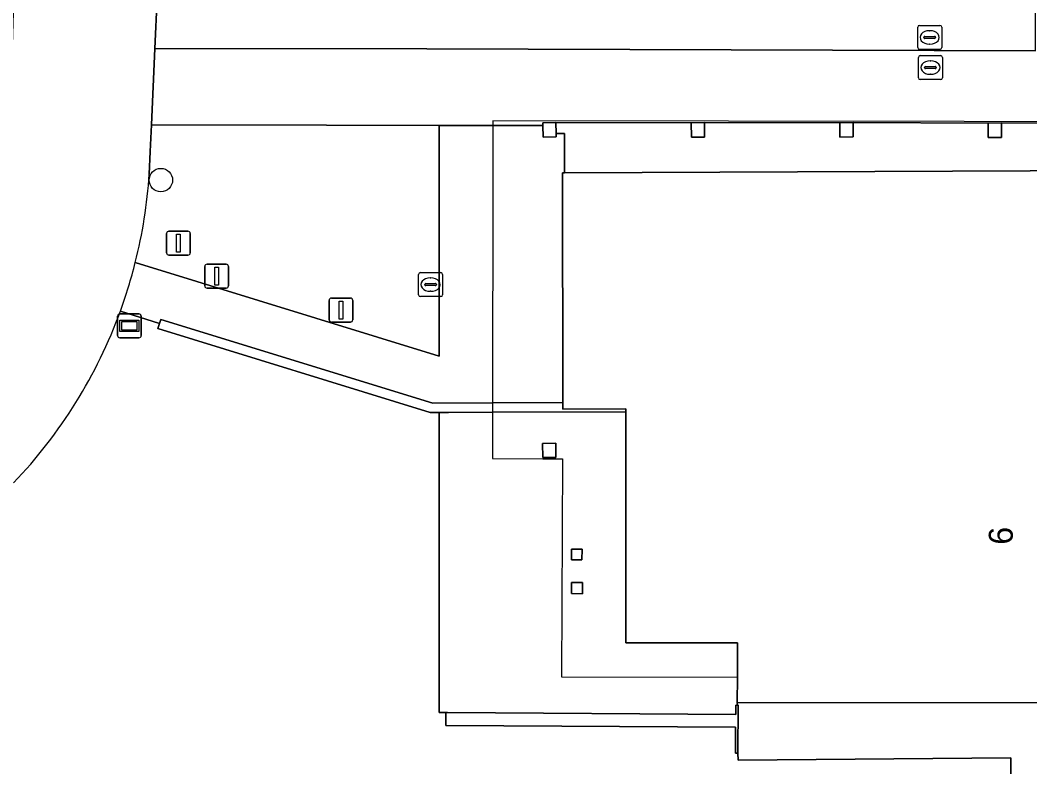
# Model space of a CAD drawing. Extents: x 161477 to 163040, y 383680 to 384871.
# Drawn here: x 161717.63 to 161759.79, y 384128.63 to 384159.8 of the extents above; entities that cross this region are included whole.
import ezdxf

# ---------------------------------------------------------------- set-up
doc = ezdxf.new("R2010")
doc.units = 0
for name, color, linetype in [('IMGEO_Boom', 7, 'Continuous'), ('IMGEO_Groenvoorziening', 7, 'Continuous'), ('IMGEO_Informatiebord', 7, 'Continuous'), ('IMGEO_Lichtmast', 7, 'Continuous'), ('IMGEO_Muur', 7, 'Continuous'), ('IMGEO_Pand', 7, 'Continuous'), ('IMGEO_Pand_nummerreeks', 7, 'Continuous'), ('IMGEO_Pand_overbouw', 7, 'Continuous'), ('IMGEO_Rioolput', 7, 'Continuous'), ('IMGEO_Vlaggenmast', 7, 'Continuous'), ('IMGEO_Voetpad_gesloten', 7, 'Continuous'), ('IMGEO_Voetpad_open', 7, 'Continuous')]:
    doc.layers.add(name, color=color, linetype=linetype)

msp = doc.modelspace()

# ---------------------------------------------------------------- linework, layer by layer
at = {"layer": 'IMGEO_Boom'}
msp.add_circle((161723.508, 384153.124), 0.489, dxfattribs=at)
at = {"layer": 'IMGEO_Groenvoorziening'}
for points in [[(161759.977, 384188.732), (161759.976, 384189.513), (161744.828, 384189.533), (161743.11, 384189.23), (161740.985, 384188.366), (161732.479, 384184.27), (161729.725, 384182.49), (161727.866, 384180.984), (161726.316, 384179.346), (161725.221, 384177.344), (161724.224, 384175.071), (161723.737, 384172.104), (161723.605, 384166.648), (161723.598, 384166.489), (161723.448, 384163.067), (161723.347, 384160.739), (161723.254, 384158.616), (161734.619, 384158.605), (161760.033, 384158.521), (161760.032, 384158.93)], [(161765.899, 384126.429), (161761.389, 384126.458), (161761.398, 384131.31), (161747.578, 384131.312), (161747.589, 384131.203), (161747.612, 384131.203), (161747.599, 384129.203), (161747.606, 384128.913), (161758.995, 384129.011), (161759.044, 384124.455), (161763.654, 384124.37), (161763.216, 384099.214), (161762.895, 384081.151), (161762.894, 384080.681), (161765.84, 384080.732)]]:
    msp.add_lwpolyline(points, close=True, dxfattribs=at)
for points in [[(161722.441, 384149.683), (161735.127, 384145.767), (161735.126, 384152.183), (161735.126, 384155.407)], [(161735.126, 384155.407), (161730.422, 384155.415), (161723.115, 384155.427), (161723.066, 384154.311), (161723.025, 384153.368)], [(161765.94, 384080.732), (161765.84, 384080.732), (161762.894, 384080.681), (161762.895, 384081.151), (161763.216, 384099.214), (161763.654, 384124.37), (161759.044, 384124.455), (161758.995, 384129.011), (161747.606, 384128.913), (161747.599, 384129.203), (161747.499, 384129.203), (161747.506, 384130.293), (161735.408, 384130.355), (161735.401, 384130.9), (161735.134, 384130.899), (161735.134, 384143.421), (161734.757, 384143.42), (161723.376, 384146.927), (161723.45, 384147.142), (161721.817, 384147.658)]]:
    msp.add_lwpolyline(points, dxfattribs=at)
for centre, radius, start, end in [((161702.337, 384154.758), 20.735, 345.8327, 356.1565), ((161702.413, 384154.74), 20.656, 316.3499, 339.9499)]:
    msp.add_arc(centre, radius, start, end, dxfattribs=at)
at = {"layer": 'IMGEO_Informatiebord'}
for p, q in [((161721.697, 384146.638), (161721.697, 384147.438)), ((161721.697, 384147.438), (161721.697, 384146.638)), ((161721.797, 384147.538), (161722.587, 384147.538)), ((161722.587, 384147.538), (161721.797, 384147.538)), ((161722.687, 384147.438), (161722.687, 384146.638)), ((161722.687, 384146.638), (161722.687, 384147.438)), ((161722.587, 384146.538), (161721.797, 384146.538)), ((161721.797, 384146.538), (161722.587, 384146.538))]:
    msp.add_line(p, q, dxfattribs=at)
for points in [[(161721.798, 384147.27), (161722.586, 384147.27), (161722.586, 384146.806), (161721.798, 384146.806), (161721.798, 384147.27)], [(161721.863, 384147.205), (161721.863, 384146.871), (161722.521, 384146.871), (161722.521, 384147.205), (161721.863, 384147.205)]]:
    msp.add_lwpolyline(points, dxfattribs=at)
for centre, start, end in [((161721.797, 384147.438), 90, 180), ((161721.797, 384147.438), 90, 180), ((161722.587, 384147.438), 0, 90), ((161722.587, 384147.438), 360, 90), ((161721.797, 384146.638), 180, 270), ((161721.797, 384146.638), 180, 270), ((161722.587, 384146.638), 270, 0), ((161722.587, 384146.638), 270, 0)]:
    msp.add_arc(centre, 0.1, start, end, dxfattribs=at)
at = {"layer": 'IMGEO_Lichtmast'}
for p, q in [((161723.745, 384150.09), (161723.745, 384150.89)), ((161723.745, 384150.89), (161723.745, 384150.09)), ((161723.845, 384150.99), (161724.635, 384150.99)), ((161724.635, 384150.99), (161723.845, 384150.99)), ((161724.735, 384150.89), (161724.735, 384150.09)), ((161724.735, 384150.09), (161724.735, 384150.89)), ((161724.635, 384149.99), (161723.845, 384149.99)), ((161723.845, 384149.99), (161724.635, 384149.99))]:
    msp.add_line(p, q, dxfattribs=at)
msp.add_lwpolyline([(161724.165, 384150.865), (161724.315, 384150.865), (161724.315, 384150.115), (161724.165, 384150.115), (161724.165, 384150.865)], dxfattribs=at)
for centre, start, end in [((161723.845, 384150.89), 90, 180), ((161723.845, 384150.89), 90, 180), ((161724.635, 384150.89), 0, 90), ((161724.635, 384150.89), 360, 90), ((161723.845, 384150.09), 180, 270), ((161723.845, 384150.09), 180, 270), ((161724.635, 384150.09), 270, 0), ((161724.635, 384150.09), 270, 0)]:
    msp.add_arc(centre, 0.1, start, end, dxfattribs=at)
at = {"layer": 'IMGEO_Muur'}
for points in [[(161723.506, 384147.305), (161723.45, 384147.142), (161723.376, 384146.927), (161734.757, 384143.42), (161735.134, 384143.421), (161735.512, 384143.423), (161737.356, 384143.43), (161742.917, 384143.452), (161742.917, 384143.573), (161740.291, 384143.568), (161740.291, 384143.838), (161737.357, 384143.825), (161734.857, 384143.814)], [(161747.612, 384131.203), (161747.589, 384131.203), (161747.512, 384131.203), (161747.51, 384130.823), (161735.483, 384130.899), (161735.401, 384130.9), (161735.408, 384130.355), (161747.506, 384130.293), (161747.499, 384129.203), (161747.599, 384129.203)]]:
    msp.add_lwpolyline(points, close=True, dxfattribs=at)
at = {"layer": 'IMGEO_Pand'}
for points in [[(161740.002, 384155.523), (161739.452, 384155.511), (161739.455, 384155.4), (161739.466, 384154.911), (161740.016, 384154.923), (161740.013, 384155.064)], [(161746.206, 384155.521), (161745.653, 384155.516), (161745.658, 384154.916), (161746.211, 384154.921)], [(161752.409, 384155.523), (161751.854, 384155.519), (161751.858, 384154.919), (161752.413, 384154.923)], [(161758.603, 384155.507), (161758.052, 384155.506), (161758.053, 384154.906), (161758.604, 384154.907)], [(161739.996, 384142.137), (161739.446, 384142.131), (161739.453, 384141.541), (161740.003, 384141.547)], [(161741.094, 384137.717), (161740.654, 384137.719), (161740.652, 384137.279), (161741.092, 384137.277)], [(161741.116, 384136.327), (161740.649, 384136.329), (161740.647, 384135.862), (161741.114, 384135.86)]]:
    msp.add_lwpolyline(points, close=True, dxfattribs=at)
msp.add_lwpolyline([(161763.052, 384153.523), (161740.363, 384153.423), (161740.284, 384153.423), (161740.291, 384143.838), (161740.291, 384143.568), (161742.917, 384143.573), (161742.917, 384143.452), (161742.924, 384133.809), (161747.583, 384133.803), (161747.58, 384132.381), (161747.578, 384131.312), (161761.398, 384131.31)], dxfattribs=at)
at = {"layer": 'IMGEO_Pand_overbouw'}
msp.add_lwpolyline([(161766.891, 384155.558), (161737.37, 384155.593), (161737.37, 384155.486), (161737.354, 384141.498), (161739.454, 384141.495), (161740.281, 384141.494), (161740.235, 384132.393), (161747.58, 384132.381), (161747.583, 384133.803), (161742.924, 384133.809), (161742.917, 384143.452), (161742.917, 384143.573), (161740.291, 384143.568), (161740.291, 384143.838), (161740.284, 384153.423), (161763.052, 384153.523)], dxfattribs=at)
at = {"layer": 'IMGEO_Rioolput'}
for p, q in [((161755.109, 384158.654), (161755.109, 384159.506)), ((161755.184, 384159.58), (161756.036, 384159.58)), ((161755.597, 384159.36), (161755.622, 384159.36)), ((161756.11, 384159.506), (161756.11, 384158.654)), ((161755.368, 384159.074), (161755.368, 384159.086)), ((161755.806, 384159.037), (161755.408, 384159.037)), ((161755.411, 384159.123), (161755.809, 384159.123)), ((161755.852, 384159.086), (161755.852, 384159.074)), ((161756.036, 384158.58), (161755.184, 384158.58)), ((161755.62, 384158.8), (161755.595, 384158.8)), ((161755.139, 384157.394), (161755.139, 384158.246)), ((161755.214, 384158.32), (161756.066, 384158.32)), ((161755.627, 384158.1), (161755.652, 384158.1)), ((161756.14, 384158.246), (161756.14, 384157.394)), ((161755.398, 384157.814), (161755.398, 384157.826)), ((161755.836, 384157.777), (161755.438, 384157.777)), ((161755.441, 384157.863), (161755.839, 384157.863)), ((161755.882, 384157.826), (161755.882, 384157.814)), ((161756.066, 384157.32), (161755.214, 384157.32)), ((161755.65, 384157.54), (161755.625, 384157.54)), ((161734.269, 384148.334), (161734.269, 384149.186)), ((161734.344, 384149.26), (161735.196, 384149.26)), ((161735.27, 384149.186), (161735.27, 384148.334)), ((161734.528, 384148.754), (161734.528, 384148.766)), ((161734.966, 384148.717), (161734.568, 384148.717)), ((161734.571, 384148.803), (161734.969, 384148.803)), ((161734.757, 384149.04), (161734.782, 384149.04)), ((161735.012, 384148.766), (161735.012, 384148.754)), ((161734.78, 384148.48), (161734.755, 384148.48)), ((161735.196, 384148.26), (161734.344, 384148.26))]:
    msp.add_line(p, q, dxfattribs=at)
for points in [[(161755.109, 384158.654), (161755.109, 384159.506)], [(161755.184, 384159.58), (161756.036, 384159.58)], [(161756.11, 384159.506), (161756.11, 384158.654)], [(161756.036, 384158.58), (161755.184, 384158.58)], [(161755.139, 384157.394), (161755.139, 384158.246)], [(161755.214, 384158.32), (161756.066, 384158.32)], [(161756.14, 384158.246), (161756.14, 384157.394)], [(161756.066, 384157.32), (161755.214, 384157.32)], [(161734.269, 384148.334), (161734.269, 384149.186)], [(161734.344, 384149.26), (161735.196, 384149.26)], [(161735.27, 384149.186), (161735.27, 384148.334)], [(161735.196, 384148.26), (161734.344, 384148.26)]]:
    msp.add_lwpolyline(points, dxfattribs=at)
for centre, radius, start, end in [((161755.186, 384159.504), 0.0765, 91.552, 178.448), ((161755.186, 384159.504), 0.0765, 91.552, 178.448), ((161756.034, 384159.504), 0.0765, 1.552, 88.448), ((161756.034, 384159.504), 0.0765, 1.552, 88.448), ((161755.408, 384159.083), 0.0403, 85.8775, 175.7526), ((161755.405, 384159.073), 0.0366, 178.938, 274.7102), ((161755.809, 384159.08), 0.043, 264.8664, 352.4533), ((161755.813, 384159.085), 0.0386, 1.7309, 96.639), ((161755.186, 384158.656), 0.0765, 181.552, 268.448), ((161755.186, 384158.656), 0.0765, 181.552, 268.448), ((161756.034, 384158.656), 0.0765, 271.552, 358.448), ((161756.034, 384158.656), 0.0765, 271.552, 358.448), ((161755.216, 384158.244), 0.0765, 91.552, 178.448), ((161755.216, 384158.244), 0.0765, 91.552, 178.448), ((161756.064, 384158.244), 0.0765, 1.552, 88.448), ((161756.064, 384158.244), 0.0765, 1.552, 88.448), ((161755.438, 384157.823), 0.0403, 85.8775, 175.7526), ((161755.435, 384157.813), 0.0366, 178.938, 274.7102), ((161755.839, 384157.82), 0.043, 264.8664, 352.4533), ((161755.843, 384157.825), 0.0386, 1.7309, 96.639), ((161755.216, 384157.396), 0.0765, 181.552, 268.448), ((161755.216, 384157.396), 0.0765, 181.552, 268.448), ((161756.064, 384157.396), 0.0765, 271.552, 358.448), ((161756.064, 384157.396), 0.0765, 271.552, 358.448), ((161734.346, 384149.184), 0.0765, 91.552, 178.448), ((161734.346, 384149.184), 0.0765, 91.552, 178.448), ((161735.194, 384149.184), 0.0765, 1.552, 88.448), ((161735.194, 384149.184), 0.0765, 1.552, 88.448), ((161734.568, 384148.763), 0.0403, 85.8775, 175.7526), ((161734.565, 384148.753), 0.0366, 178.938, 274.7102), ((161734.969, 384148.76), 0.043, 264.8664, 352.4533), ((161734.973, 384148.765), 0.0386, 1.7309, 96.639), ((161734.346, 384148.336), 0.0765, 181.552, 268.448), ((161734.346, 384148.336), 0.0765, 181.552, 268.448), ((161735.194, 384148.336), 0.0765, 271.552, 358.448), ((161735.194, 384148.336), 0.0765, 271.552, 358.448)]:
    msp.add_arc(centre, radius, start, end, dxfattribs=at)
for centre, major_axis, ratio, start_param, end_param in [((161755.596, 384159.08), (-0.387, 0.002), 0.722429, 4.712389, 7.853982), ((161755.621, 384159.08), (-0.39, 0.002), 0.717154, 1.570796, 4.712389), ((161755.626, 384157.82), (-0.387, 0.002), 0.722429, 4.712389, 7.853982), ((161755.651, 384157.82), (-0.39, 0.002), 0.717154, 1.570796, 4.712389), ((161734.756, 384148.76), (-0.387, 0.002), 0.722429, 4.712389, 7.853982), ((161734.781, 384148.76), (-0.39, 0.002), 0.717154, 1.570796, 4.712389)]:
    msp.add_ellipse(centre, major_axis=major_axis, ratio=ratio, start_param=start_param, end_param=end_param, dxfattribs=at)
at = {"layer": 'IMGEO_Vlaggenmast'}
for p, q in [((161725.441, 384149.613), (161726.231, 384149.613)), ((161726.231, 384149.613), (161725.441, 384149.613)), ((161725.341, 384148.713), (161725.341, 384149.513)), ((161725.341, 384149.513), (161725.341, 384148.713)), ((161726.331, 384149.513), (161726.331, 384148.713)), ((161726.331, 384148.713), (161726.331, 384149.513)), ((161726.231, 384148.613), (161725.441, 384148.613)), ((161725.441, 384148.613), (161726.231, 384148.613)), ((161730.529, 384147.296), (161730.529, 384148.096)), ((161730.529, 384148.096), (161730.529, 384147.296)), ((161730.629, 384148.196), (161731.419, 384148.196)), ((161731.419, 384148.196), (161730.629, 384148.196)), ((161731.519, 384148.096), (161731.519, 384147.296)), ((161731.519, 384147.296), (161731.519, 384148.096)), ((161731.419, 384147.196), (161730.629, 384147.196)), ((161730.629, 384147.196), (161731.419, 384147.196))]:
    msp.add_line(p, q, dxfattribs=at)
for points in [[(161725.761, 384149.488), (161725.911, 384149.488), (161725.911, 384148.738), (161725.761, 384148.738), (161725.761, 384149.488)], [(161730.949, 384148.071), (161731.099, 384148.071), (161731.099, 384147.321), (161730.949, 384147.321), (161730.949, 384148.071)]]:
    msp.add_lwpolyline(points, dxfattribs=at)
for centre, start, end in [((161725.441, 384149.513), 90, 180), ((161725.441, 384149.513), 90, 180), ((161726.231, 384149.513), 0, 90), ((161726.231, 384149.513), 360, 90), ((161725.441, 384148.713), 180, 270), ((161725.441, 384148.713), 180, 270), ((161726.231, 384148.713), 270, 0), ((161726.231, 384148.713), 270, 0), ((161730.629, 384148.096), 90, 180), ((161730.629, 384148.096), 90, 180), ((161731.419, 384148.096), 0, 90), ((161731.419, 384148.096), 360, 90), ((161730.629, 384147.296), 180, 270), ((161730.629, 384147.296), 180, 270), ((161731.419, 384147.296), 270, 0), ((161731.419, 384147.296), 270, 0)]:
    msp.add_arc(centre, 0.1, start, end, dxfattribs=at)
at = {"layer": 'IMGEO_Voetpad_gesloten'}
msp.add_lwpolyline([(161723.025, 384153.368), (161723.066, 384154.311), (161723.115, 384155.427), (161723.254, 384158.616), (161723.347, 384160.739), (161723.448, 384163.067), (161723.598, 384166.489), (161723.605, 384166.648), (161723.737, 384172.104), (161724.224, 384175.071), (161725.221, 384177.344), (161726.316, 384179.346), (161727.866, 384180.984), (161729.725, 384182.49), (161713.664, 384175.843), (161715.148, 384175.981), (161716.3, 384175.582), (161717.185, 384174.608), (161717.547, 384171.536), (161717.584, 384167.817), (161717.198, 384155.593)], dxfattribs=at)
for centre, radius, start, end in [((161702.337, 384154.758), 20.735, 345.8327, 356.1565), ((161702.531, 384154.71), 20.535, 339.9159, 345.8309), ((161702.413, 384154.74), 20.656, 316.3499, 339.9499)]:
    msp.add_arc(centre, radius, start, end, dxfattribs=at)
at = {"layer": 'IMGEO_Voetpad_open'}
for points in [[(161760.033, 384158.521), (161734.619, 384158.605), (161723.254, 384158.616), (161723.115, 384155.427), (161730.422, 384155.415), (161735.126, 384155.407), (161737.37, 384155.403), (161739.455, 384155.4), (161739.452, 384155.511), (161740.002, 384155.523), (161745.653, 384155.516), (161746.206, 384155.521), (161751.854, 384155.519), (161752.409, 384155.523), (161758.052, 384155.506), (161758.603, 384155.507), (161764.245, 384155.504)], [(161764.245, 384155.504), (161758.603, 384155.507), (161758.604, 384154.907), (161758.053, 384154.906), (161758.052, 384155.506), (161752.409, 384155.523), (161752.413, 384154.923), (161751.858, 384154.919), (161751.854, 384155.519), (161746.206, 384155.521), (161746.211, 384154.921), (161745.658, 384154.916), (161745.653, 384155.516), (161740.002, 384155.523), (161740.013, 384155.064), (161740.155, 384155.064), (161740.355, 384155.065), (161740.363, 384153.423), (161763.052, 384153.523)], [(161721.817, 384147.658), (161723.45, 384147.142), (161723.506, 384147.305), (161734.857, 384143.814), (161737.357, 384143.825), (161740.291, 384143.838), (161740.284, 384153.423), (161740.363, 384153.423), (161740.355, 384155.065), (161740.155, 384155.064), (161740.013, 384155.064), (161740.016, 384154.923), (161739.466, 384154.911), (161739.455, 384155.4), (161737.37, 384155.403), (161735.126, 384155.407), (161735.126, 384152.183), (161735.127, 384145.767), (161722.441, 384149.683)]]:
    msp.add_lwpolyline(points, dxfattribs=at)
for points in [[(161742.917, 384143.452), (161737.356, 384143.43), (161735.512, 384143.423), (161735.134, 384143.421), (161735.134, 384130.899), (161735.401, 384130.9), (161735.483, 384130.899), (161747.51, 384130.823), (161747.512, 384131.203), (161747.589, 384131.203), (161747.578, 384131.312), (161747.58, 384132.381), (161747.583, 384133.803), (161742.924, 384133.809)], [(161739.453, 384141.541), (161739.446, 384142.131), (161739.996, 384142.137), (161740.003, 384141.547)], [(161740.652, 384137.279), (161740.654, 384137.719), (161741.094, 384137.717), (161741.092, 384137.277)], [(161741.116, 384136.327), (161741.114, 384135.86), (161740.647, 384135.862), (161740.649, 384136.329)]]:
    msp.add_lwpolyline(points, close=True, dxfattribs=at)
msp.add_arc((161702.531, 384154.71), 20.535, 339.9159, 345.8309, dxfattribs=at)

# ---------------------------------------------------------------- texts
at = {"layer": 'IMGEO_Pand_nummerreeks'}
msp.add_text('6', height=1, rotation=89.7538, dxfattribs=at).set_placement((161759.076, 384137.903))

doc.saveas('drawing.dxf')
